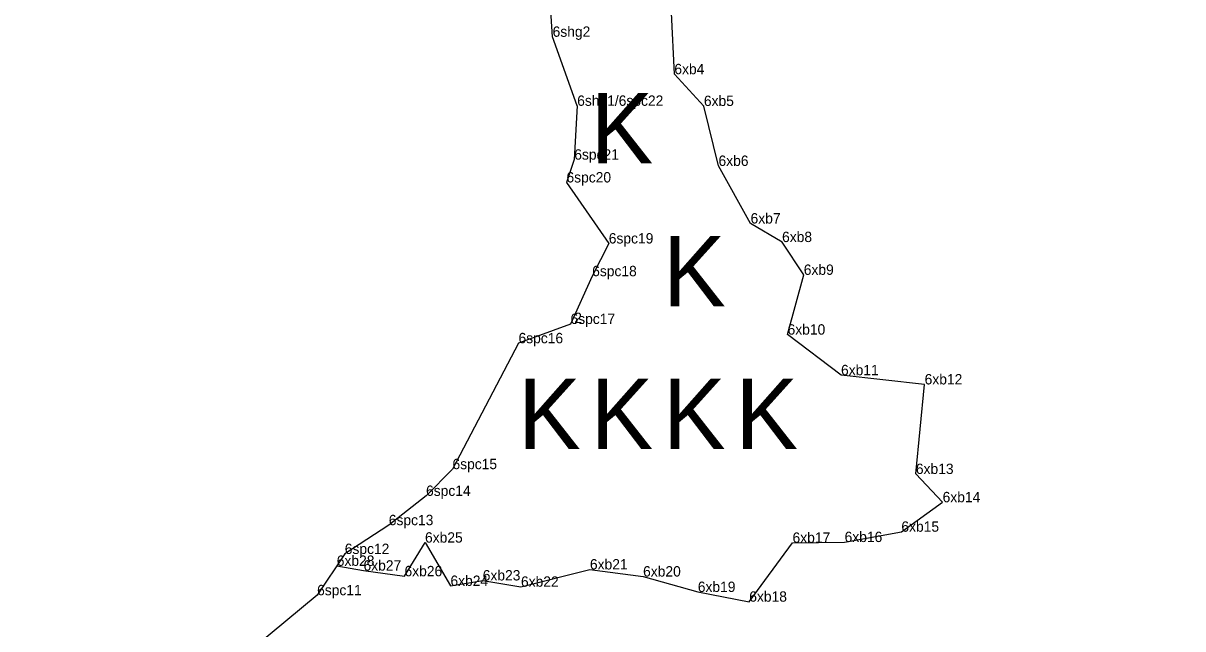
# Model space of a CAD drawing. Extents: x 2072529 to 2268812, y 436423 to 470008.
# Drawn here: x 2142578 to 2143138, y 444780 to 445072 of the extents above; entities that cross this region are included whole.
import ezdxf

# ---------------------------------------------------------------- set-up
doc = ezdxf.new("R2010")
doc.units = 0
for name, color, linetype in [('Old_Level_10', 7, 'Continuous'), ('Old_Level_20', 7, 'Continuous'), ('Old_Level_52', 7, 'Continuous'), ('Old_Level_55', 7, 'Continuous'), ('Old_Level_60', 7, 'Continuous')]:
    doc.layers.add(name, color=color, linetype=linetype)

msp = doc.modelspace()

# ---------------------------------------------------------------- linework, layer by layer
at = {"layer": 'Old_Level_10'}
for points in [[(2142845.684, 445032.461), (2142833.82, 445065.802), (2142830.34, 445118.293), (2142826.246, 445152.85), (2142835.15, 445199.722), (2142839.266, 445234.219), (2142868.024, 445248.349), (2142895.296, 445261.945), (2142914.547, 445248.145), (2142972.754, 445262.866), (2143013.208, 445264.578), (2143052.072, 445270.711), (2143139.229, 445286.64)], [(2142845.684, 445032.461), (2142844.279, 445006.459), (2142840.508, 444995.441), (2142860.952, 444965.965), (2142852.921, 444950.168), (2142842.473, 444927.075), (2142817.341, 444917.788)], [(2142817.341, 444917.788), (2142785.427, 444856.964), (2142772.659, 444844.072), (2142754.657, 444829.913), (2142733.385, 444815.999), (2142720.022, 444796.076)], [(2142720.022, 444796.076), (2142675.586, 444759.271), (2142665.472, 444728.407), (2142642.166, 444699.764), (2142627.903, 444680.25), (2142618.25, 444665.649), (2142601.709, 444621.249), (2142586.327, 444561.184), (2142580.18, 444498.299), (2142581.26, 444474.419), (2142578.004, 444443.679)]]:
    msp.add_lwpolyline(points, dxfattribs=at)
at = {"layer": 'Old_Level_20'}
for p, q in [((2142833.82, 445065.802), (2142833.82, 445065.802)), ((2142892.652, 445047.734), (2142892.652, 445047.734)), ((2142845.684, 445032.461), (2142845.684, 445032.461)), ((2142906.924, 445032.372), (2142906.924, 445032.372)), ((2142844.279, 445006.459), (2142844.279, 445006.459)), ((2142913.98, 445003.441), (2142913.98, 445003.441)), ((2142840.508, 444995.441), (2142840.508, 444995.441)), ((2142929.483, 444975.622), (2142929.483, 444975.622)), ((2142860.952, 444965.965), (2142860.952, 444965.965)), ((2142944.695, 444966.659), (2142944.695, 444966.659)), ((2142852.921, 444950.168), (2142852.921, 444950.168)), ((2142955.18, 444950.823), (2142955.18, 444950.823)), ((2142842.473, 444927.075), (2142842.473, 444927.075)), ((2142947.356, 444921.952), (2142947.356, 444921.952)), ((2142817.341, 444917.788), (2142817.341, 444917.788)), ((2142973.19, 444902.348), (2142973.19, 444902.348)), ((2143013.585, 444897.902), (2143013.585, 444897.902)), ((2142785.427, 444856.964), (2142785.427, 444856.964)), ((2143009.35, 444854.64), (2143009.35, 444854.64)), ((2142772.659, 444844.072), (2142772.659, 444844.072)), ((2143022.276, 444840.994), (2143022.276, 444840.994)), ((2142754.657, 444829.913), (2142754.657, 444829.913)), ((2143002.352, 444826.752), (2143002.352, 444826.752)), ((2142772.171, 444821.493), (2142772.171, 444821.493)), ((2142949.752, 444821.418), (2142949.752, 444821.418)), ((2142974.914, 444821.773), (2142974.914, 444821.773)), ((2142733.385, 444815.999), (2142733.385, 444815.999)), ((2142729.513, 444810.239), (2142729.513, 444810.239)), ((2142742.45, 444807.967), (2142742.45, 444807.967)), ((2142851.853, 444808.533), (2142851.853, 444808.533)), ((2142762.256, 444805.256), (2142762.256, 444805.256)), ((2142800.058, 444803.212), (2142800.058, 444803.212)), ((2142877.537, 444805.119), (2142877.537, 444805.119)), ((2142720.022, 444796.076), (2142720.022, 444796.076)), ((2142784.456, 444800.592), (2142784.456, 444800.592)), ((2142818.536, 444800.184), (2142818.536, 444800.184)), ((2142903.966, 444797.661), (2142903.966, 444797.661)), ((2142928.837, 444792.955), (2142928.837, 444792.955))]:
    msp.add_line(p, q, dxfattribs=at)
at = {"layer": 'Old_Level_52'}
msp.add_lwpolyline([(2142729.52, 444810.273), (2142742.45, 444807.967), (2142762.256, 444805.256), (2142772.171, 444821.493), (2142784.456, 444800.592), (2142800.058, 444803.212), (2142818.536, 444800.184), (2142851.853, 444808.533), (2142877.537, 444805.119), (2142903.966, 444797.661), (2142928.837, 444792.955), (2142949.752, 444821.418), (2142974.914, 444821.773), (2143002.352, 444826.752), (2143022.276, 444840.994), (2143009.35, 444854.64), (2143013.585, 444897.902), (2142973.19, 444902.348), (2142947.356, 444921.952), (2142955.18, 444950.823), (2142944.695, 444966.659), (2142929.483, 444975.622), (2142913.98, 445003.441), (2142906.924, 445032.372), (2142892.652, 445047.734), (2142891.283, 445077.431)], dxfattribs=at)

# ---------------------------------------------------------------- texts
at = {"layer": 'Old_Level_55'}
for p in [(2142852.121, 445004.656), (2142887.121, 444935.656), (2142817.121, 444866.656), (2142852.121, 444866.656), (2142887.121, 444866.656), (2142922.121, 444866.656)]:
    msp.add_text('K', height=34, dxfattribs=at).set_placement(p)
at = {"layer": 'Old_Level_60'}
for s, p in [('6shg2', (2142833.82, 445065.802)), ('6xb4', (2142892.652, 445047.734)), ('6shg1/6spc22', (2142845.684, 445032.461)), ('6xb5', (2142906.924, 445032.372)), ('6spc21', (2142844.279, 445006.459)), ('6xb6', (2142913.98, 445003.441)), ('6spc20', (2142840.508, 444995.441)), ('6xb7', (2142929.483, 444975.622)), ('6spc19', (2142860.952, 444965.965)), ('6xb8', (2142944.695, 444966.659)), ('6spc18', (2142852.921, 444950.168)), ('6xb9', (2142955.18, 444950.823)), ('6spc17', (2142842.473, 444927.075)), ('2', (2142844.279, 444927.55)), ('6xb10', (2142947.356, 444921.952)), ('6spc16', (2142817.341, 444917.788)), ('6xb11', (2142973.19, 444902.348)), ('6xb12', (2143013.585, 444897.902)), ('6spc15', (2142785.427, 444856.964)), ('6xb13', (2143009.35, 444854.64)), ('6spc14', (2142772.659, 444844.072)), ('6xb14', (2143022.276, 444840.994)), ('6spc13', (2142754.657, 444829.913)), ('6xb15', (2143002.352, 444826.752)), ('6xb25', (2142772.171, 444821.493)), ('6xb17', (2142949.752, 444821.418)), ('6xb16', (2142974.914, 444821.773)), ('6spc12', (2142733.385, 444815.999)), ('6xb28', (2142729.52, 444810.273)), ('6xb27', (2142742.45, 444807.967)), ('6xb21', (2142851.853, 444808.533)), ('6xb26', (2142762.256, 444805.256)), ('6xb23', (2142800.058, 444803.212)), ('6xb20', (2142877.537, 444805.119)), ('6xb24', (2142784.456, 444800.592)), ('6xb22', (2142818.536, 444800.184)), ('6xb19', (2142903.966, 444797.661)), ('6spc11', (2142720.022, 444796.076)), ('6xb18', (2142928.837, 444792.955))]:
    msp.add_text(s, height=5, dxfattribs=at).set_placement(p)

doc.saveas('drawing.dxf')
